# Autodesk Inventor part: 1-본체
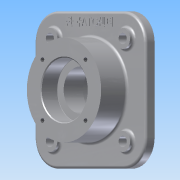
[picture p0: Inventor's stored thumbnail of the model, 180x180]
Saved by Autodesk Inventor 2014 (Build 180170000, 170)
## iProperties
Created: 2015-09
Part Number: 1-본체
Material: 알루미늄 6061
Document SubType Name: Modeling
Designer: study
Density: 2.71 g/cm^3
Appearance: 알루미늄 - 평지
Mass: 1464.68 g
Surface Area: 800.934 cm^2
Volume: 540.471 cm^3
Author: study
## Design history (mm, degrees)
sketch "스케치1"
  geometry: L1 (-75, 75)-(75, 75); L2 (75, 75)-(75, -75); L3 (75, -75)-(-75, -75); L4 (-75, -75)-(-75, 75); L5 (-75, 75)-(75, -75); L6 (75, 75)-(-75, -75); 1 further point
  constraints: 12 end point, 2 midpoint, 2 parallel, 2 perpendicular, 1 horizontal
  dimensions: "d0" = 150 distance of L1.start L1.end
extrude "돌출1" new body sketch "스케치1" distance "d1" = 12; taper "d2" = 0 deg
sketch "스케치2"
  geometry: C1 r 50 at (0, 0); 1 further point
  constraints: 1 centre point, 1 coincident
  dimensions: "d3" = 100 diameter of C1
extrude "돌출2" join sketch "스케치2" distance "d4" = 23; taper "d5" = 0 deg
node "작업 평면1"
sketch "스케치3"
  geometry: C1 r 50 at (0, 0) reference; 1 further point
extrude "돌출3" join sketch "스케치3" stored distance "d7" = 23; taper "d8" = 0 deg
hole "구멍1" diameter "d11" = 45; stored, may be unused: countersink angle "d15" = 90 deg, drill point angle "d17" = 118 deg; dims "d9" = 10, "d10" = 10, "d12" = 6, "d13" = 62, "d14" = 22, "d16" = 8
hole "구멍2" diameter "d20" = 45; stored, may be unused: countersink angle "d24" = 90 deg, drill point angle "d26" = 118 deg; dims "d18" = 10, "d19" = 10, "d21" = 6, "d22" = 62, "d23" = 22, "d25" = 8
sketch "스케치4"
  geometry: C1 r 50 at (0, 0) reference; C2 r 10 at (-49, 49)
  constraints: 1 centre point
  dimensions: "d27" = 20 diameter of C2; "d28" = 49 horizontal distance of C1.centre C2.centre; "d29" = 49 horizontal distance of C1.centre C2.centre
extrude "돌출4" join sketch "스케치4" distance "d30" = 5; taper "d31" = 0 deg
hole "구멍3" diameter "d34" = 11; stored, may be unused: countersink angle "d38" = 90 deg, drill point angle "d40" = 118 deg; dims "d32" = 10, "d33" = 10, "d35" = 6, "d36" = 62, "d37" = 22, "d39" = 8
sketch "스케치5"
  geometry: L1 (-28.991, -28.991)-(28.991, -28.991); L2 (28.991, -28.991)-(28.991, 28.991); L3 (28.991, 28.991)-(-28.991, 28.991); L4 (-28.991, 28.991)-(-28.991, -28.991); L5 (-28.991, -28.991)-(28.991, 28.991); L6 (28.991, -28.991)-(-28.991, 28.991); C1 r 50 at (0, 0) reference; 4 further points
  constraints: 12 end point, 4 coincident, 2 midpoint, 2 parallel, 2 perpendicular, 1 horizontal
  dimensions: "d44" = 82 distance of L2.end L1.start
hole "구멍4" sketch "스케치5" at (-28.991, 28.991), (-28.991, -28.991), (28.991, -28.991), (28.991, 28.991) diameter "d45" = 4.917; stored, may be unused: countersink angle "d49" = 90 deg, drill point angle "d51" = 118 deg; dims "d46" = 10, "d47" = 62, "d48" = 22, "d50" = 13
node "작업 평면2"
fillet "모깎기1" dims "d52" = 30
fillet "모깎기2" dims "d53" = 3, "d54" = 0.3
chamfer "모따기1" distance "d55" = 1; stored, may be unused: second distance "d56" = 2, angle "d57" = 45 deg
sketch "스케치6"
  geometry: C1 r 53 at (0, 0) reference; 1 further point
  constraints: 1 vertical alignment, 1 other
  dimensions: "d61" = 65 distance of C1.centre point (0, 65)
feature "엠보싱1" sketch "스케치6" dims "d59" = 1, "d60" = 0
node "솔리드1"
pattern_circular "원형 패턴1" dims angle "d42" = 360 deg
mirror "대칭1"
